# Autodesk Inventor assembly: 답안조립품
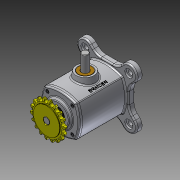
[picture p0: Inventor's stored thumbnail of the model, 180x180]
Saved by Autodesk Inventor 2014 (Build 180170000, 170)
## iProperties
Created: 2016-05
Part Number: 답안조립품
Document SubType Name: Assembly
Designer: S. S. MOON
Author: S. S. MOON
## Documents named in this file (11)
- C:\Users\Administrator\Desktop\460507V1022\답안조립품.iam
- C:\Users\Administrator\Desktop\460507V1022\본체.ipt
- C:\Users\Administrator\Desktop\460507V1022\M4x0.7x12.ipt
- C:\Users\Administrator\Desktop\460507V1022\베어링-6203.ipt
- C:\Users\Administrator\Desktop\460507V1022\부시.ipt
- C:\Users\Administrator\Desktop\460507V1022\스프로킷.ipt
- C:\Users\Administrator\Desktop\460507V1022\슬라이더.ipt
- C:\Users\Administrator\Desktop\460507V1022\오일실.ipt
- C:\Users\Administrator\Desktop\460507V1022\커버.ipt
- C:\Users\Administrator\Desktop\460507V1022\키5x5.ipt
- C:\Users\Administrator\Desktop\460507V1022\편심축.ipt
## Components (8 placed, 1 different names)
1. M4x0.7x12:1
2. M4x0.7x12:3
3. M4x0.7x12:4
4. M4x0.7x12:5
5. M4x0.7x12:2
6. M4x0.7x12:6
7. M4x0.7x12:7
8. M4x0.7x12:8
